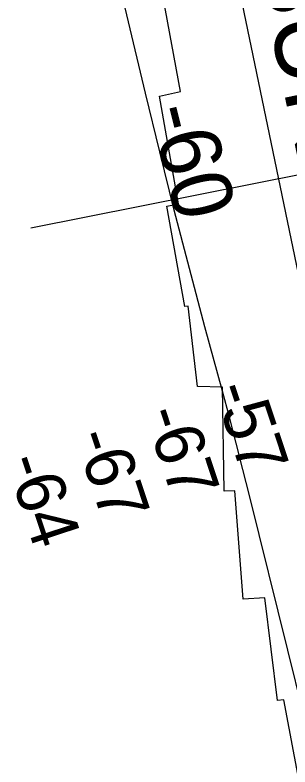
# Model space of a CAD drawing. Extents: x 3405885 to 3443815, y 558517 to 583997.
# Drawn here: x 3414616 to 3414990, y 580124 to 581149 of the extents above; entities that cross this region are included whole.
import ezdxf

# ---------------------------------------------------------------- set-up
doc = ezdxf.new("R2010")
doc.units = 0
for name, color, linetype in [('V-RIVR-RANG', 7, 'Continuous'), ('V-RRAP-RVMT', 7, 'Continuous'), ('V-RRAP-RVMT-IDEN', 7, 'Continuous'), ('V-TOPO-MAJR', 7, 'Continuous'), ('V-TOPO-MINR', 7, 'Continuous'), ('V-TOPO-MINR-IDEN', 7, 'Continuous')]:
    doc.layers.add(name, color=color, linetype=linetype)

msp = doc.modelspace()

# ---------------------------------------------------------------- linework, layer by layer
at = {"layer": 'V-RIVR-RANG'}
msp.add_line((3415402.2, 581010.2), (3414637.1, 580858.5), dxfattribs=at)
at = {"layer": 'V-RRAP-RVMT'}
for p, q in [((3414840.9, 581044.9), (3414814.9, 581186.5)), ((3414812.4, 581038.6), (3414840.9, 581044.9)), ((3414838.3, 580891.4), (3414812.4, 581038.6)), ((3414822.3, 580888.6), (3414838.3, 580891.4)), ((3414847.1, 580751.8), (3414822.3, 580888.6)), ((3414851.5, 580752), (3414847.1, 580751.8)), ((3414864.5, 580642.6), (3414851.5, 580752)), ((3414898.2, 580641.7), (3414864.5, 580642.6)), ((3414900.5, 580499.8), (3414898.2, 580641.7)), ((3414915.3, 580500.4), (3414900.5, 580499.8)), ((3414926.6, 580352.5), (3414915.3, 580500.4)), ((3414956, 580354.5), (3414926.6, 580352.5)), ((3414973.2, 580214.3), (3414956, 580354.5)), ((3414982.2, 580215.4), (3414973.2, 580214.3)), ((3415008.5, 580074.1), (3414982.2, 580215.4))]:
    msp.add_line(p, q, dxfattribs=at)
at = {"layer": 'V-TOPO-MAJR'}
msp.add_lwpolyline([(3414910.2, 581236.4), (3415040.9, 580605.9), (3415041.2, 580604.4), (3415042, 580599.9), (3415043.1, 580593.2), (3415043.3, 580591.7), (3415043.4, 580590.2), (3415043.6, 580587.2), (3415043.8, 580582.6), (3415168.2, 579815.2), (3415171.9, 579799.2), (3415175.7, 579783.3), (3415179.5, 579767.4), (3415183.4, 579751.5), (3415187.3, 579735.6), (3415191.2, 579719.8), (3415195, 579703.9), (3415198.8, 579687.9), (3415361.2, 579001.7)], dxfattribs=at)
at = {"layer": 'V-TOPO-MINR'}
msp.add_lwpolyline([(3415179.5, 579513.9), (3415129, 579711.6), (3415122.1, 579738.7), (3415115.3, 579765.8), (3415108.5, 579792.9), (3415101.8, 579820.1), (3415072.6, 579938.1), (3415051.3, 580024.3), (3415030, 580110.5), (3415008.7, 580196.7), (3414987.4, 580282.8), (3414935.3, 580493.7), (3414926.3, 580529.3), (3414917.2, 580565), (3414907.8, 580600.5), (3414898.3, 580636), (3414874.5, 580723.8), (3414853.3, 580803.3), (3414832.6, 580882.8), (3414812.8, 580962.6), (3414793.4, 581042.6), (3414742.6, 581256.6)], dxfattribs=at)

# ---------------------------------------------------------------- texts
at = {"layer": 'V-RIVR-RANG'}
for s, p in [('-57', (3414885.7, 580639.2)), ('-67', (3414791.3, 580606)), ('-67', (3414696.3, 580574.8)), ('-64', (3414602.2, 580540.9))]:
    msp.add_text(s, height=67, rotation=288.3019, dxfattribs=at).set_placement(p)
at = {"layer": 'V-RRAP-RVMT-IDEN'}
msp.add_text('BURN-', height=100, rotation=281.7608, dxfattribs=at).set_placement((3414943.5, 581229))
at = {"layer": 'V-TOPO-MINR-IDEN'}
msp.add_text('-60', height=83, rotation=283.9968, dxfattribs=at).set_placement((3414798.5, 581019.8))

doc.saveas('drawing.dxf')
